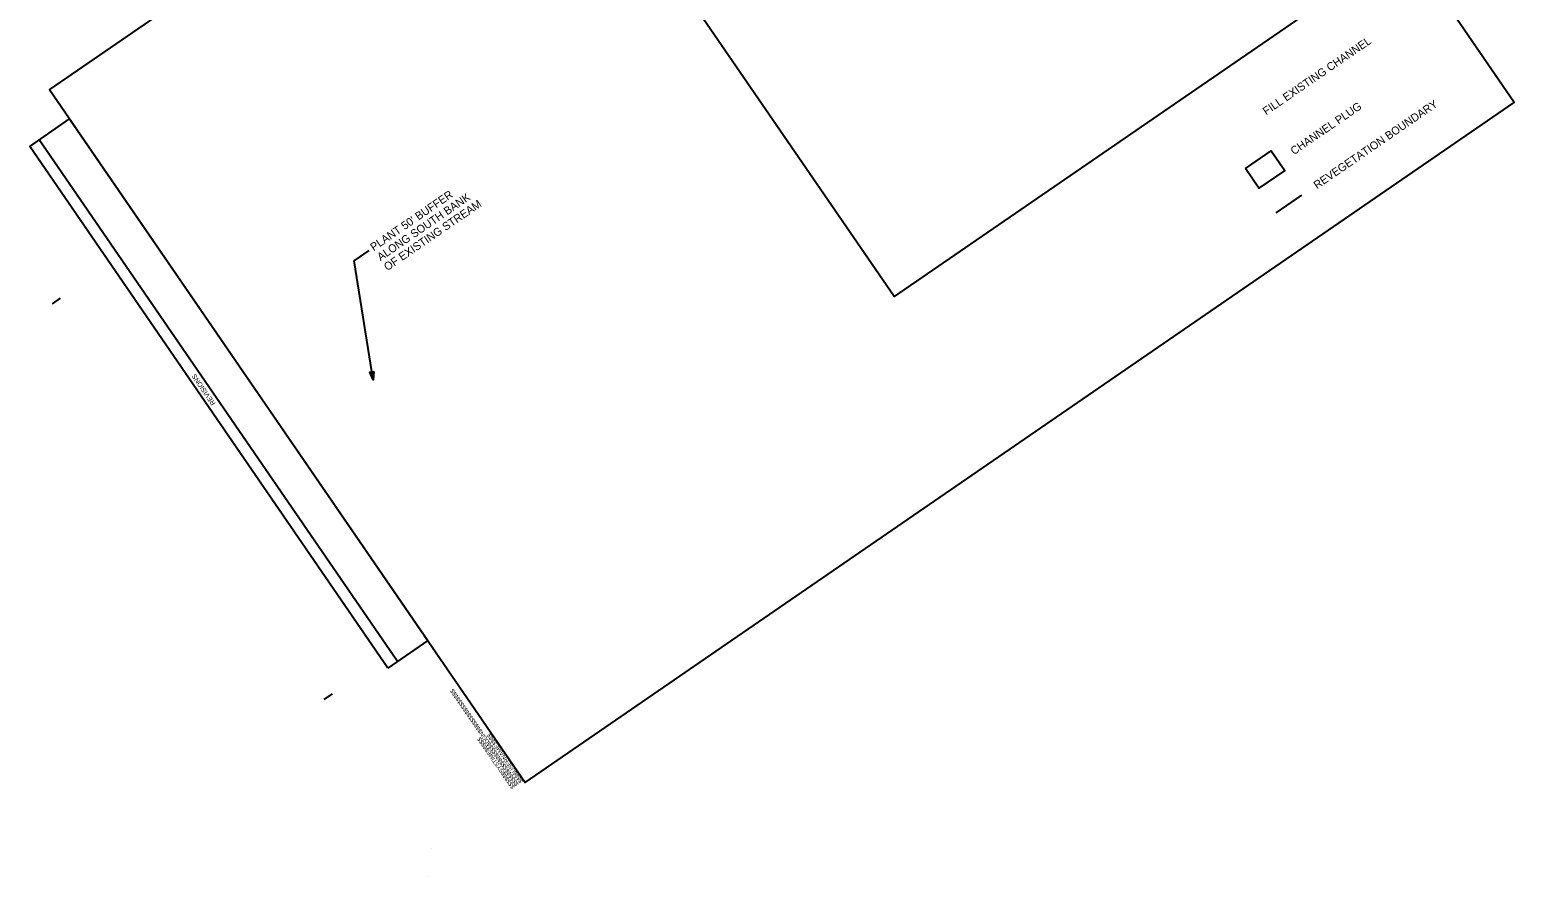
# Model space of a CAD drawing. Extents: x 2385901 to 2398444, y 552503 to 560579.
# Drawn here: x 2394733 to 2398444, y 556859 to 558974 of the extents above; entities that cross this region are included whole.
import ezdxf

# ---------------------------------------------------------------- set-up
doc = ezdxf.new("R2010")
doc.units = 0
for name, color, linetype in [('Old_Level_23', 7, 'Continuous'), ('Old_Level_50', 7, 'Continuous'), ('Old_Level_52', 7, 'Continuous'), ('Old_Level_8', 7, 'Continuous'), ('Prop EOT', 7, 'Continuous'), ('Prop Horizontal Alignment Tick Large', 7, 'Continuous'), ('Prop ROW CA Lines', 7, 'Continuous'), ('Prop ROW Marker Iron Pin and Cap CELL', 7, 'Continuous'), ('Prop ROW RW CA Lines', 7, 'Continuous'), ('Prop ROW Station Offsets', 7, 'Continuous')]:
    doc.layers.add(name, color=color, linetype=linetype)

msp = doc.modelspace()

# ---------------------------------------------------------------- linework, layer by layer
at = {"layer": 'Old_Level_23'}
for p, q in [((2394789.2, 558289.3), (2394809.8, 558303.5)), ((2395468.7, 557300.2), (2395489.3, 557314.4))]:
    msp.add_line(p, q, dxfattribs=at)
at = {"layer": 'Old_Level_50'}
msp.add_line((2395726.9, 556858.9), (2395726.9, 556858.9), dxfattribs=at)
at = {"layer": 'Old_Level_52'}
msp.add_line((2395738.2, 556927.3), (2395738.2, 556927.3), dxfattribs=at)
at = {"layer": 'Old_Level_8'}
msp.add_line((2395651.8, 557395.7), (2394756.5, 558699.1), dxfattribs=at)
msp.add_lwpolyline([(2395627.9, 557379.2), (2394732.5, 558682.6), (2394832.3, 558751.2), (2395727.6, 557447.8)], close=True, dxfattribs=at)
at = {"layer": 'Prop EOT'}
msp.add_line((2395971.1, 557093.3), (2395971.1, 557093.3), dxfattribs=at)
msp.add_lwpolyline([(2397255, 560522.9), (2394782.1, 558824.3), (2395971.1, 557093.3), (2398443.9, 558791.9)], close=True, dxfattribs=at)
at = {"layer": 'Prop Horizontal Alignment Tick Large'}
msp.add_line((2397848.2, 558516.2), (2397912.6, 558560.5), dxfattribs=at)
at = {"layer": 'Prop ROW CA Lines'}
msp.add_lwpolyline([(2397771.9, 558627.3), (2397836.4, 558671.6), (2397870.1, 558622.4), (2397805.6, 558578.1)], close=True, dxfattribs=at)
at = {"layer": 'Prop ROW Marker Iron Pin and Cap CELL'}
for p, q in [((2395543.5, 558396.7), (2395581, 558422.5)), ((2395591.1, 558099.5), (2395543.5, 558396.7))]:
    msp.add_line(p, q, dxfattribs=at)
msp.add_lwpolyline([(2395592.8, 558120.1), (2395591.1, 558099.5), (2395583, 558118.5)], close=True, dxfattribs=at)
at = {"layer": 'Prop ROW RW CA Lines'}
msp.add_lwpolyline([(2396323.9, 559136.9), (2397107.8, 559675.4), (2397182.9, 559566.1), (2397427.9, 559734.4), (2397466.7, 559677.8), (2397606.2, 559773.6), (2398061.8, 559110.3), (2396893.4, 558307.7)], close=True, dxfattribs=at)

# ---------------------------------------------------------------- texts
at = {"layer": 'Old_Level_23'}
for s, p in [('$$$$$$$$$$$$$$$$DGN$$$$$$$$$$$$$$$$', (2395955.8, 557088.6)), ('$$$$$$SYSTIME$$$$$', (2395945.8, 557081.7)), ('$$$$USERNAME$$$$', (2395966.6, 557096))]:
    msp.add_text(s, height=10.5, rotation=124.4849, dxfattribs=at).set_placement(p)
at = {"layer": 'Old_Level_8'}
msp.add_text('REVISIONS', height=12, rotation=124.4849, dxfattribs=at).set_placement((2395197.7, 558040.5))
at = {"layer": 'Prop ROW Marker Iron Pin and Cap CELL'}
for s, p in [("PLANT 50' BUFFER", (2395592.6, 558420.1)), ('ALONG SOUTH BANK', (2395609.6, 558395.4)), ('OF EXISTING STREAM', (2395626.6, 558370.6))]:
    msp.add_text(s, height=20, rotation=34.4849, dxfattribs=at).set_placement(p)
at = {"layer": 'Prop ROW Station Offsets'}
for s, p in [('FILL EXISTING CHANNEL', (2397823.7, 558759.7)), ('CHANNEL PLUG', (2397893, 558660.3)), ('REVEGETATION BOUNDARY', (2397950.7, 558575.1))]:
    msp.add_text(s, height=20, rotation=34.4745, dxfattribs=at).set_placement(p)

doc.saveas('drawing.dxf')
